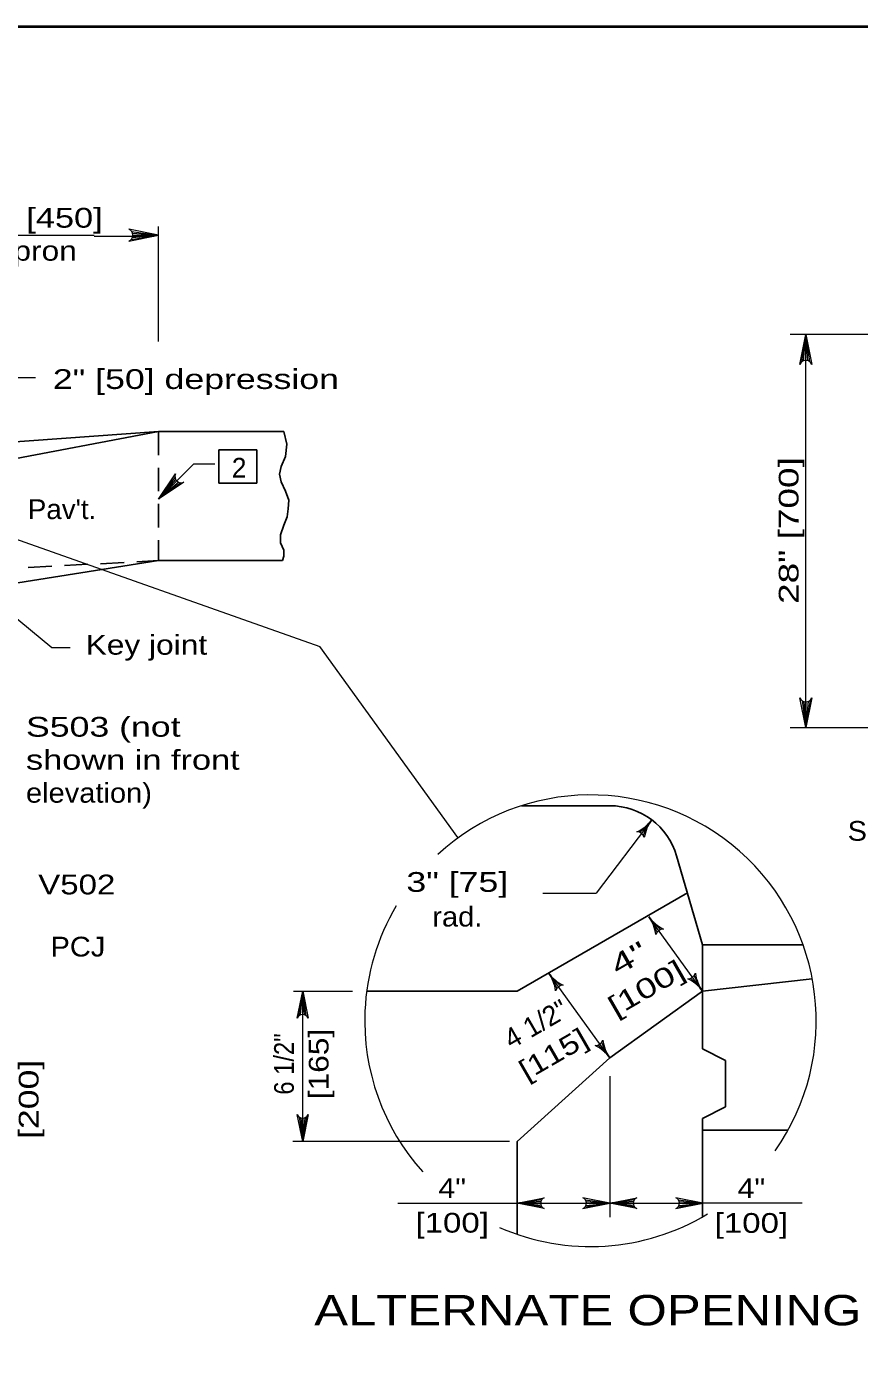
# Model space of a CAD drawing. Extents: x 339.1 to 373.1, y 1412.7 to 1456.7.
# Drawn here: x 349.27 to 355.85, y 1423.77 to 1434.25 of the extents above; entities that cross this region are included whole.
import ezdxf
from ezdxf.enums import TextEntityAlignment as Align

# ---------------------------------------------------------------- set-up
doc = ezdxf.new("R2010")
doc.units = 0
doc.header["$LTSCALE"] = 0.062
doc.linetypes.add('MEDIUM_DASHED', pattern=[4.5, 3, -1.5])
doc.layers.add('1', color=7, linetype='Continuous', lineweight=13)

msp = doc.modelspace()

# ---------------------------------------------------------------- linework, layer by layer
at = {"layer": '1', "lineweight": 25}
for p, q in [((341.0605, 1434.2455), (372.5605, 1434.2455)), ((348.42217, 1430.68892), (350.30792, 1431.04758)), ((348.42217, 1430.91067), (350.30792, 1431.04758)), ((350.30792, 1431.04758), (351.29692, 1431.04758)), ((348.424, 1429.72975), (350.30775, 1430.02767)), ((350.30775, 1430.02767), (351.289, 1430.02767)), ((353.17508, 1428.09208), (353.87375, 1428.09208)), ((354.6055, 1426.99467), (354.40058, 1427.697)), ((353.14208, 1426.62883), (354.48608, 1427.40475)), ((355.47342, 1426.72533), (354.6055, 1426.629)), ((351.95283, 1426.62883), (353.14208, 1426.62883)), ((354.6055, 1426.17175), (354.78842, 1426.08025)), ((354.78842, 1425.71442), (354.78842, 1426.08025)), ((354.6055, 1425.623), (354.78842, 1425.71442)), ((354.6055, 1424.84583), (354.6055, 1425.623)), ((355.28175, 1425.5315), (354.60475, 1425.5315)), ((353.14208, 1424.7075), (353.14208, 1425.43983))]:
    msp.add_line(p, q, dxfattribs=at)
at = {"layer": '1'}
for p, q in [((350.09542, 1432.62742), (350.30875, 1432.59758)), ((350.10267, 1432.61267), (350.30875, 1432.59758)), ((350.30875, 1431.75708), (350.30875, 1432.665)), ((348.424, 1432.59758), (349.80033, 1432.59758)), ((349.80033, 1432.59025), (350.27042, 1432.59025)), ((350.09292, 1432.56458), (350.30875, 1432.59758)), ((350.10108, 1432.57842), (350.30875, 1432.59758)), ((350.10483, 1432.59758), (350.30875, 1432.59758)), ((357.98283, 1431.81325), (355.29933, 1431.81325)), ((355.38967, 1431.59742), (355.42267, 1431.81325)), ((355.4035, 1431.60558), (355.42267, 1431.81325)), ((355.42267, 1430.518), (355.42267, 1431.81325)), ((355.42267, 1431.60933), (355.42267, 1431.81325)), ((355.43775, 1431.60717), (355.42267, 1431.81325)), ((355.4525, 1431.59992), (355.42267, 1431.81325)), ((350.43833, 1430.68525), (350.30775, 1430.51392)), ((350.44358, 1430.66967), (350.30775, 1430.51392)), ((350.45258, 1430.65742), (350.30775, 1430.51392)), ((350.46875, 1430.64642), (350.30775, 1430.51392)), ((350.48433, 1430.64233), (350.30775, 1430.51392)), ((355.42267, 1428.70933), (355.42267, 1430.518)), ((348.95742, 1430.277), (351.58392, 1429.34875)), ((352.67383, 1427.84192), (351.58392, 1429.34875)), ((355.39283, 1428.92258), (355.42267, 1428.70933)), ((355.40758, 1428.91542), (355.42267, 1428.70933)), ((355.45567, 1428.92517), (355.42267, 1428.70933)), ((355.44183, 1428.917), (355.42267, 1428.70933)), ((355.42267, 1428.91317), (355.42267, 1428.70933)), ((355.29933, 1428.70933), (357.76242, 1428.70933)), ((354.20525, 1427.98067), (353.76625, 1427.40183)), ((353.345, 1427.40183), (353.76625, 1427.40183)), ((354.6055, 1426.629), (354.18167, 1427.216)), ((353.87375, 1426.10083), (353.3895, 1426.77175)), ((351.37492, 1426.62883), (351.8415, 1426.62883)), ((351.41742, 1426.43267), (351.44742, 1426.62883)), ((351.43, 1426.44008), (351.44742, 1426.62883)), ((351.44742, 1425.43983), (351.44742, 1426.62883)), ((351.44742, 1426.4435), (351.44742, 1426.62883)), ((351.46108, 1426.4415), (351.44742, 1426.62883)), ((351.4745, 1426.43492), (351.44742, 1426.62883)), ((353.87375, 1425.95542), (353.87375, 1424.84275)), ((351.42025, 1425.63375), (351.44742, 1425.43983)), ((351.43367, 1425.62717), (351.44742, 1425.43983)), ((351.47742, 1425.636), (351.44742, 1425.43983)), ((351.46483, 1425.62858), (351.44742, 1425.43983)), ((351.44742, 1425.62517), (351.44742, 1425.43983)), ((353.08058, 1425.43983), (351.36875, 1425.43983)), ((353.336, 1424.98108), (353.14208, 1424.954)), ((353.32942, 1424.96767), (353.14208, 1424.954)), ((353.67983, 1424.98108), (353.87375, 1424.954)), ((353.68642, 1424.96767), (353.87375, 1424.954)), ((354.06767, 1424.98108), (353.87375, 1424.954)), ((354.06108, 1424.96767), (353.87375, 1424.954)), ((354.41508, 1424.98108), (354.609, 1424.954)), ((354.42167, 1424.96767), (354.609, 1424.954)), ((352.19792, 1424.954), (353.65842, 1424.954)), ((353.32742, 1424.954), (353.14208, 1424.954)), ((353.33083, 1424.93658), (353.14208, 1424.954)), ((353.33825, 1424.924), (353.14208, 1424.954)), ((353.67758, 1424.924), (353.87375, 1424.954)), ((353.685, 1424.93658), (353.87375, 1424.954)), ((353.68842, 1424.954), (353.87375, 1424.954)), ((354.05908, 1424.954), (353.87375, 1424.954)), ((354.0625, 1424.93658), (353.87375, 1424.954)), ((354.06992, 1424.924), (353.87375, 1424.954)), ((354.41283, 1424.924), (354.609, 1424.954)), ((354.42025, 1424.93658), (354.609, 1424.954)), ((354.42367, 1424.954), (354.609, 1424.954)), ((355.39275, 1424.954), (354.609, 1424.954))]:
    msp.add_line(p, q, dxfattribs=at)
at = {"layer": '1', "linetype": 'MEDIUM_DASHED', "lineweight": 25}
for p in [(350.30775, 1431.04758), (348.42208, 1429.92925)]:
    msp.add_line(p, (350.30775, 1430.02767), dxfattribs=at)
at = {"layer": '1', "lineweight": 40}
msp.add_lwpolyline([(341.0605, 1434.2455), (372.5605, 1434.2455), (372.5605, 1413.2455), (341.0605, 1413.2455)], close=True, dxfattribs=at)
at = {"layer": '1'}
for points in [[(350.07317, 1432.55042), (350.30875, 1432.59758), (350.07317, 1432.64467)], [(355.37558, 1431.57767), (355.42267, 1431.81325), (355.46975, 1431.57767)], [(348.42217, 1430.76358), (349.12, 1431.47433), (349.33642, 1431.47433)], [(350.30775, 1430.51392), (350.58792, 1430.791), (350.75383, 1430.791)], [(350.50833, 1430.64625), (350.30775, 1430.51392), (350.442, 1430.71317)], [(348.52658, 1430.11658), (349.46492, 1429.34283), (349.61083, 1429.34283)], [(355.46975, 1428.94492), (355.42267, 1428.70933), (355.37558, 1428.94492)], [(351.40458, 1426.41467), (351.44742, 1426.62883), (351.49025, 1426.41467)], [(351.49025, 1425.654), (351.44742, 1425.43983), (351.40458, 1425.654)], [(353.35625, 1424.91117), (353.14208, 1424.954), (353.35625, 1424.99683)], [(353.65958, 1424.91117), (353.87375, 1424.954), (353.65958, 1424.99683)], [(354.08792, 1424.91117), (353.87375, 1424.954), (354.08792, 1424.99683)], [(354.39483, 1424.91117), (354.609, 1424.954), (354.39483, 1424.99683)], [(353.65842, 1424.954), (353.87375, 1424.954), (354.6055, 1424.954)]]:
    msp.add_lwpolyline(points, dxfattribs=at)
at = {"layer": '1', "lineweight": 25}
for points in [[(351.29692, 1431.04758), (351.32142, 1430.94867), (351.31267, 1430.84925), (351.2775, 1430.77167), (351.26283, 1430.70958), (351.2775, 1430.6505), (351.31267, 1430.576), (351.339, 1430.50458), (351.33317, 1430.43617), (351.32433, 1430.37417), (351.298, 1430.30892), (351.27158, 1430.23125), (351.27158, 1430.16917), (351.298, 1430.11017), (351.298, 1430.0635), (351.289, 1430.02767)], [(354.6055, 1426.17175), (354.6055, 1426.99467), (355.40025, 1426.99467)], [(354.6055, 1426.629), (353.87375, 1426.10083), (353.14208, 1425.43983)]]:
    msp.add_lwpolyline(points, dxfattribs=at)
msp.add_lwpolyline([(350.785, 1430.90158), (350.785, 1430.63992), (351.08367, 1430.63992), (351.08367, 1430.90158)], close=True, dxfattribs=at)
at = {"layer": '1'}
for centre, radius, start, end in [((350.05412, 1432.59761), 0.05085, 292.08605, 67.91218), ((355.42271, 1431.5586), 0.05085, 22.08782, 157.91395), ((350.48863, 1430.69313), 0.05085, 156.81909, 292.64521), ((355.42261, 1428.96395), 0.05085, 202.08782, 337.91395), ((351.44746, 1426.39738), 0.04623, 22.08782, 157.91395), ((351.44736, 1425.6713), 0.04623, 202.08782, 337.91395), ((353.37354, 1424.95405), 0.04623, 112.08782, 247.91395), ((353.64231, 1424.95405), 0.04623, 292.08605, 67.91218), ((354.10524, 1424.95405), 0.04623, 112.08782, 247.91395), ((354.37755, 1424.95405), 0.04623, 292.08605, 67.91218)]:
    msp.add_arc(centre, radius, start, end, dxfattribs=at)
for centre, major_axis, ratio, start_param, end_param in [((353.72085, 1426.39431), (1.78353, 0), 0.999895, 5.66940401, 8.59713226), ((353.94861, 1428.1794), (0.32471, 0), 0.999895, 5.15498111, 5.62381242), ((354.07795, 1428.08118), (0.20163, 0.25449), 0.500117, 4.27696671, 4.7128289), ((354.33666, 1427.885), (-0.1907, -0.26277), 0.500121, 4.70982398, 5.14829141), ((354.46038, 1427.78975), (-0.31868, 0), 0.999895, 5.6407634, 6.11911999), ((354.08772, 1427.82551), (-0.06049, 0), 0.999895, 3.41408403, 4.71307422), ((353.72085, 1426.39431), (1.78353, 0), 0.999895, 2.60773478, 3.09878016), ((354.31162, 1427.31369), (-0.19557, 0.25917), 0.500119, 1.56809713, 2.00656456), ((354.43889, 1427.40414), (-0.31868, 0), 0.999895, 0.63163034, 1.10998693), ((353.91659, 1427.02872), (0.32471, 0), 0.999895, 0.14584805, 0.61467936), ((354.04835, 1427.12367), (-0.18445, 0.26719), 0.500123, 4.27683276, 4.71269495), ((354.29572, 1427.05826), (-0.06049, 0), 0.999895, 4.68813632, 5.98712651), ((353.51943, 1426.86946), (0.19556, -0.25918), 0.500119, 4.70968978, 5.14815721), ((353.64671, 1426.9599), (-0.31868, 0), 0.999895, 0.63158302, 1.10993962), ((353.12439, 1426.58451), (0.32471, 0), 0.999895, 0.14580073, 0.61463205), ((353.25615, 1426.67945), (-0.18444, 0.2672), 0.500123, 4.27683276, 4.71269495), ((354.49146, 1426.78671), (0.06049, 0), 0.999895, 4.68813622, 5.98712642), ((354.73883, 1426.7213), (0.18445, -0.26719), 0.500123, 4.27683276, 4.71269495), ((354.87058, 1426.81625), (-0.32471, 0), 0.999895, 0.1458481, 0.61467941), ((353.50352, 1426.61403), (-0.06049, 0), 0.999895, 4.68808891, 5.9870791), ((354.34828, 1426.44083), (0.31868, 0), 0.999895, 0.63163034, 1.10998693), ((354.47556, 1426.53128), (0.19557, -0.25917), 0.500119, 1.56809713, 2.00656456), ((353.72085, 1426.39431), (1.78353, 0), 0.999895, 3.09878118, 3.87453364), ((353.75976, 1426.2586), (0.06049, 0), 0.999895, 4.68808891, 5.9870791), ((354.00713, 1426.19318), (0.18444, -0.2672), 0.500123, 4.27683276, 4.71269495), ((354.13889, 1426.28812), (-0.32471, 0), 0.999895, 0.14580073, 0.61463205), ((353.61657, 1425.91273), (0.31868, 0), 0.999895, 0.63158302, 1.10993962), ((353.74385, 1426.00317), (-0.19556, 0.25918), 0.500119, 4.70968978, 5.14815721), ((353.72085, 1426.39431), (1.78353, 0), 0.999895, 4.29826525, 5.25687552)]:
    msp.add_ellipse(centre, major_axis=major_axis, ratio=ratio, start_param=start_param, end_param=end_param, dxfattribs=at)
at = {"layer": '1', "lineweight": 25}
msp.add_ellipse((353.87377, 1427.54333), major_axis=(0.54878, 0), ratio=0.999895, start_param=0.28379403, end_param=1.57079623, dxfattribs=at)

# ---------------------------------------------------------------- texts
at = {"layer": '1'}
for s, height, width, p in [('18" [450]', 0.156, 1.3, (349.32867, 1432.657)), ('Apron', 0.156, 1.2, (349.32879, 1432.39633)), ('3" [75]', 0.156, 1.35, (352.66867, 1427.41233)), ('rad.', 0.156, 1.1, (352.66875, 1427.13833)), ('4"', 0.156, 1.15, (352.62829, 1424.99517)), ('4"', 0.156, 1.15, (354.99187, 1424.99358)), ('[100]', 0.156, 1.25, (352.62837, 1424.72117)), ('[100]', 0.156, 1.25, (354.99196, 1424.71958)), ('ALTERNATE OPENING', 0.24, 1.25, (353.70037, 1423.989))]:
    msp.add_text(s, height=height, dxfattribs=dict(at, width=width)).set_placement(p, align=Align.CENTER)
for s, width, p in [('2" [50] depression', 1.35, (349.47308, 1431.38342)), ("Pav't.", 1.05, (349.27583, 1430.35592)), ('Key joint', 1.2, (349.73242, 1429.28508)), ('S503 (not', 1.35, (349.26108, 1428.63758)), ('shown in front', 1.3, (349.26108, 1428.37692)), ('elevation)', 1.1, (349.26108, 1428.11625)), ('S601', 1.1, (355.752, 1427.81567)), ('V502', 1.25, (349.35783, 1427.39225)), ('PCJ', 1.1, (349.45458, 1426.90158))]:
    msp.add_text(s, height=0.156, dxfattribs=dict(at, width=width)).set_placement(p)
msp.add_text('2', height=0.156, dxfattribs=at).set_placement((350.887, 1430.68342))
at = {"layer": '1', "width": 1.4}
msp.add_text('28" [700]', height=0.156, rotation=90, dxfattribs=at).set_placement((355.36442, 1429.6855))
at = {"layer": '1'}
for s, rotation, width, p in [('4"', 29.997, 1.55, (354.06279, 1426.82238)), ('[100]', 29.997, 1.4, (354.19971, 1426.58503)), ('[115]', 29.997, 1.25, (353.466, 1426.06442)), ('6 1/2"', 90, 0.9, (351.37742, 1426.05258)), ('[165]', 90, 1.2, (351.65142, 1426.05271)), ('[200]', 90, 1.35, (349.36025, 1425.77354))]:
    msp.add_text(s, height=0.156, rotation=rotation, dxfattribs=dict(at, width=width)).set_placement(p, align=Align.CENTER)
msp.add_text('4 1/2"', height=0.156, rotation=29.997, dxfattribs=at).set_placement((353.32909, 1426.30175), align=Align.CENTER)

doc.saveas('drawing.dxf')
